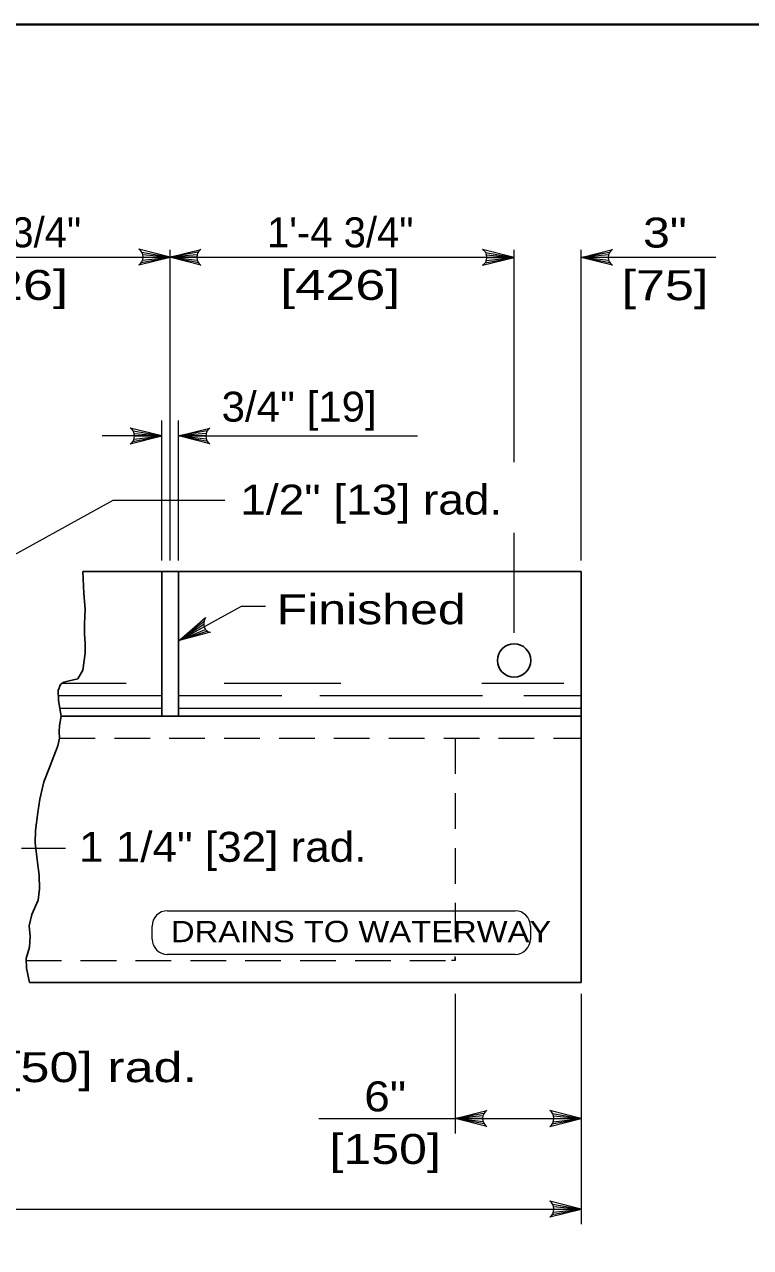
# Model space of a CAD drawing. Extents: x 1352.5 to 1386.5, y 735.9 to 779.9.
# Drawn here: x 1361.98 to 1365.77, y 751.05 to 757.42 of the extents above; entities that cross this region are included whole.
import ezdxf
from ezdxf.enums import TextEntityAlignment as Align

# ---------------------------------------------------------------- set-up
doc = ezdxf.new("R2010")
doc.units = 0
doc.header["$LTSCALE"] = 0.062
doc.linetypes.add('MEDIUM_DASHED', pattern=[4.5, 3, -1.5])
doc.layers.add('1', color=7, linetype='Continuous', lineweight=13)

msp = doc.modelspace()

# ---------------------------------------------------------------- linework, layer by layer
at = {"layer": '1', "lineweight": 25}
for p, q in [((1354.513, 757.41967), (1386.013, 757.41967)), ((1364.88517, 754.56975), (1362.28883, 754.56975)), ((1362.69958, 754.56975), (1362.69958, 753.81775)), ((1362.787, 754.56975), (1362.787, 753.81775)), ((1364.88517, 752.42942), (1364.88517, 754.56975)), ((1362.17525, 753.81775), (1364.88517, 753.81775)), ((1362.00958, 752.42942), (1364.88517, 752.42942))]:
    msp.add_line(p, q, dxfattribs=at)
at = {"layer": '1'}
for p, q in [((1362.74325, 754.62758), (1362.74325, 756.24592)), ((1364.5355, 755.13942), (1364.5355, 756.24592)), ((1364.88517, 754.62758), (1364.88517, 756.24592)), ((1364.5355, 756.20658), (1357.36675, 756.20658)), ((1362.59367, 756.1795), (1362.74383, 756.20817)), ((1362.59542, 756.23417), (1362.74383, 756.20817)), ((1362.59942, 756.1915), (1362.74383, 756.20817)), ((1362.6005, 756.22133), (1362.74383, 756.20817)), ((1362.602, 756.20817), (1362.74383, 756.20817)), ((1362.88842, 756.23317), (1362.74, 756.20725)), ((1362.88342, 756.22033), (1362.74, 756.20725)), ((1362.88192, 756.20725), (1362.74, 756.20725)), ((1362.8845, 756.19058), (1362.74, 756.20725)), ((1362.89017, 756.17858), (1362.74, 756.20725)), ((1364.38533, 756.17792), (1364.5355, 756.20658)), ((1364.38708, 756.23258), (1364.5355, 756.20658)), ((1364.391, 756.18992), (1364.5355, 756.20658)), ((1364.39208, 756.21975), (1364.5355, 756.20658)), ((1364.39358, 756.20658), (1364.5355, 756.20658)), ((1365.03358, 756.23258), (1364.88517, 756.20658)), ((1365.0285, 756.21975), (1364.88517, 756.20658)), ((1365.027, 756.20658), (1364.88517, 756.20658)), ((1365.02967, 756.18992), (1364.88517, 756.20658)), ((1365.03533, 756.17792), (1364.88517, 756.20658)), ((1365.58792, 756.20658), (1364.88517, 756.20658)), ((1362.69958, 754.62758), (1362.69958, 755.35642)), ((1362.787, 754.62758), (1362.787, 755.35642)), ((1362.55117, 755.30225), (1362.69958, 755.27625)), ((1362.55617, 755.28942), (1362.69958, 755.27625)), ((1362.93542, 755.30225), (1362.787, 755.27625)), ((1362.93033, 755.28942), (1362.787, 755.27625)), ((1362.69958, 755.27625), (1362.38883, 755.27625)), ((1362.54942, 755.24758), (1362.69958, 755.27625)), ((1362.55508, 755.25958), (1362.69958, 755.27625)), ((1362.55775, 755.27625), (1362.69958, 755.27625)), ((1362.787, 755.27625), (1364.03183, 755.27625)), ((1362.92883, 755.27625), (1362.787, 755.27625)), ((1362.93142, 755.25958), (1362.787, 755.27625)), ((1362.93717, 755.24758), (1362.787, 755.27625)), ((1364.5355, 754.25158), (1364.5355, 754.77142)), ((1362.91883, 754.30867), (1362.79075, 754.21142)), ((1362.91825, 754.29442), (1362.79075, 754.21142)), ((1362.921, 754.28158), (1362.79075, 754.21142)), ((1362.92875, 754.26758), (1362.79075, 754.21142)), ((1362.93775, 754.25942), (1362.79075, 754.21142)), ((1362.17525, 753.98942), (1362.51483, 753.98942)), ((1363.0255, 753.98942), (1363.63208, 753.98942)), ((1364.36808, 753.98942), (1364.79492, 753.98942)), ((1362.16042, 753.92408), (1362.69958, 753.92408)), ((1362.787, 753.92408), (1363.32517, 753.92408)), ((1363.52417, 753.92408), (1364.3705, 753.92408)), ((1364.58633, 753.92408), (1364.88517, 753.92408)), ((1362.16842, 753.85875), (1362.69958, 753.85875)), ((1362.787, 753.85875), (1364.88517, 753.85875)), ((1362.19833, 753.128), (1361.96833, 753.128)), ((1362.72908, 752.80325), (1364.54083, 752.80325)), ((1362.64908, 752.65617), (1362.64908, 752.72325)), ((1364.62083, 752.72325), (1364.62083, 752.65617)), ((1364.54083, 752.57617), (1362.72908, 752.57617)), ((1364.2295, 752.54508), (1364.20892, 752.54508)), ((1364.2295, 752.54508), (1364.2295, 752.56458)), ((1364.2295, 752.3715), (1364.2295, 751.64275)), ((1364.88517, 752.3715), (1364.88517, 751.17075)), ((1363.51767, 751.72142), (1364.88517, 751.72142)), ((1364.37792, 751.74733), (1364.2295, 751.72142)), ((1364.37283, 751.7345), (1364.2295, 751.72142)), ((1364.37133, 751.72142), (1364.2295, 751.72142)), ((1364.37392, 751.70475), (1364.2295, 751.72142)), ((1364.37967, 751.69275), (1364.2295, 751.72142)), ((1364.735, 751.69275), (1364.88517, 751.72142)), ((1364.73675, 751.74733), (1364.88517, 751.72142)), ((1364.74067, 751.70475), (1364.88517, 751.72142)), ((1364.74175, 751.7345), (1364.88517, 751.72142)), ((1364.74333, 751.72142), (1364.88517, 751.72142)), ((1364.73675, 751.27533), (1364.88517, 751.24942)), ((1357.017, 751.24942), (1364.88517, 751.24942)), ((1364.735, 751.22067), (1364.88517, 751.24942)), ((1364.74067, 751.23275), (1364.88517, 751.24942)), ((1364.74175, 751.2625), (1364.88517, 751.24942)), ((1364.74333, 751.24942), (1364.88517, 751.24942))]:
    msp.add_line(p, q, dxfattribs=at)
at = {"layer": '1', "linetype": 'MEDIUM_DASHED'}
for p, q in [((1362.16683, 753.70208), (1364.88517, 753.70208)), ((1364.2295, 753.70208), (1364.2295, 752.54508)), ((1361.99083, 752.54508), (1364.2295, 752.54508))]:
    msp.add_line(p, q, dxfattribs=at)
at = {"layer": '1', "lineweight": 40}
msp.add_lwpolyline([(1354.513, 757.41967), (1386.013, 757.41967), (1386.013, 736.41967), (1354.513, 736.41967)], close=True, dxfattribs=at)
msp.add_lwpolyline([(1354.513, 757.41967), (1386.013, 757.41967), (1386.013, 736.41967), (1354.513, 736.41967)], close=True, dxfattribs=at)
at = {"layer": '1'}
for points in [[(1362.57992, 756.16725), (1362.74383, 756.20817), (1362.57992, 756.24917)], [(1362.904, 756.16625), (1362.74, 756.20725), (1362.904, 756.24825)], [(1364.37158, 756.16567), (1364.5355, 756.20658), (1364.37158, 756.24758)], [(1365.04908, 756.16567), (1364.88517, 756.20658), (1365.04908, 756.24758)], [(1362.53567, 755.23525), (1362.69958, 755.27625), (1362.53567, 755.31725)], [(1362.95092, 755.23525), (1362.787, 755.27625), (1362.95092, 755.31725)], [(1361.79592, 754.58492), (1362.44575, 754.94258), (1363.02867, 754.94258)], [(1362.79075, 754.21142), (1363.11508, 754.38992), (1363.24025, 754.38992)], [(1362.95425, 754.25492), (1362.79075, 754.21142), (1362.92833, 754.33017)], [(1364.39342, 751.68042), (1364.2295, 751.72142), (1364.39342, 751.76242)], [(1364.72125, 751.68042), (1364.88517, 751.72142), (1364.72125, 751.76242)], [(1364.72125, 751.20842), (1364.88517, 751.24942), (1364.72125, 751.29042)]]:
    msp.add_lwpolyline(points, dxfattribs=at)
at = {"layer": '1', "lineweight": 25}
msp.add_lwpolyline([(1362.28883, 754.56975), (1362.2935, 754.45633), (1362.30025, 754.37392), (1362.29658, 754.2975), (1362.29767, 754.24608), (1362.3005, 754.19475), (1362.29983, 754.14442), (1362.28825, 754.0565), (1362.26158, 754.01083), (1362.21617, 754.00075), (1362.18908, 753.99392), (1362.17242, 753.98133), (1362.15892, 753.95058), (1362.16175, 753.89808), (1362.17525, 753.81775), (1362.16617, 753.76892), (1362.164, 753.73692), (1362.167, 753.70275), (1362.15867, 753.66167), (1362.13708, 753.60908), (1362.11458, 753.54983), (1362.08575, 753.47558), (1362.06458, 753.38542), (1362.05325, 753.31467), (1362.04158, 753.22108), (1362.03983, 753.157), (1362.05242, 753.05542), (1362.06025, 752.98792), (1362.06283, 752.91717), (1362.056, 752.85892), (1362.022, 752.78358), (1362.00808, 752.72425), (1362.0135, 752.66933), (1362.01017, 752.61342), (1361.99367, 752.55525), (1361.99392, 752.50383), (1362.00958, 752.42942)], dxfattribs=at)
msp.add_circle((1364.53547, 754.10698), 0.08677, dxfattribs=at)
at = {"layer": '1'}
for centre, start, end in [((1362.72908, 752.72325), 90, 180), ((1364.54076, 752.72325), 0, 90), ((1362.72908, 752.65617), 180, 270), ((1364.54076, 752.65617), 270, 0)]:
    msp.add_arc(centre, 0.08, start, end, dxfattribs=at)
for centre, start_param, end_param in [((1362.56668, 756.20825), 3.5270669, 5.8976801), ((1362.9172, 756.2073), 0.3855052, 2.7561184), ((1364.35831, 756.20666), 3.5270669, 5.8976801), ((1365.06232, 756.20666), 0.3855052, 2.7561184), ((1362.52241, 755.27631), 3.5270669, 5.8976801), ((1362.96415, 755.27631), 0.3855052, 2.7561184), ((1362.95343, 754.29914), 0.7927706, 3.1633838), ((1364.40664, 751.72144), 0.3855052, 2.7561184), ((1364.708, 751.72144), 3.5270669, 5.8976801), ((1364.708, 751.24944), 3.5270669, 5.8976801)]:
    msp.add_ellipse(centre, major_axis=(0, 0.04422), ratio=0.8, start_param=start_param, end_param=end_param, dxfattribs=at)

# ---------------------------------------------------------------- texts
for p in [(1361.89779, 756.259), (1363.62979, 756.259)]:
    msp.add_text('1\'-4 3/4"', height=0.156, dxfattribs=at).set_placement(p, align=Align.CENTER)
for s, width, p in [('3"', 1.2, (1365.32204, 756.25758)), ('[426]', 1.35, (1361.89779, 755.985)), ('[426]', 1.35, (1363.62979, 755.985)), ('[75]', 1.3, (1365.32204, 755.98358)), ('6"', 1.15, (1363.86392, 751.75858)), ('[150]', 1.25, (1363.86392, 751.48458))]:
    msp.add_text(s, height=0.156, dxfattribs=dict(at, width=width)).set_placement(p, align=Align.CENTER)
for s, height, width, p in [('3/4" [19]', 0.156, 1.05, (1363.01133, 755.35092)), ('1/2" [13] rad.', 0.156, 1.15, (1363.10867, 754.86692)), ('Finished', 0.156, 1.25, (1363.298, 754.29575)), ('1 1/4" [32] rad.', 0.156, 1.1, (1362.26875, 753.05833)), ('DRAINS TO WATERWAY   ', 0.111, 1.15, (1362.7475, 752.63975)), ('2" [50] rad.', 0.156, 1.3, (1361.56567, 751.91067))]:
    msp.add_text(s, height=height, dxfattribs=dict(at, width=width)).set_placement(p)

doc.saveas('drawing.dxf')
